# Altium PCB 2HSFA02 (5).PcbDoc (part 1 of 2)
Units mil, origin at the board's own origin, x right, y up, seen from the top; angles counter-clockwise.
Board outline 4391.67 x 3028.12 mil, 2 copper layers (Top Layer, Bottom Layer); 97 components, 133 nets, 219 pads, 38 vias.
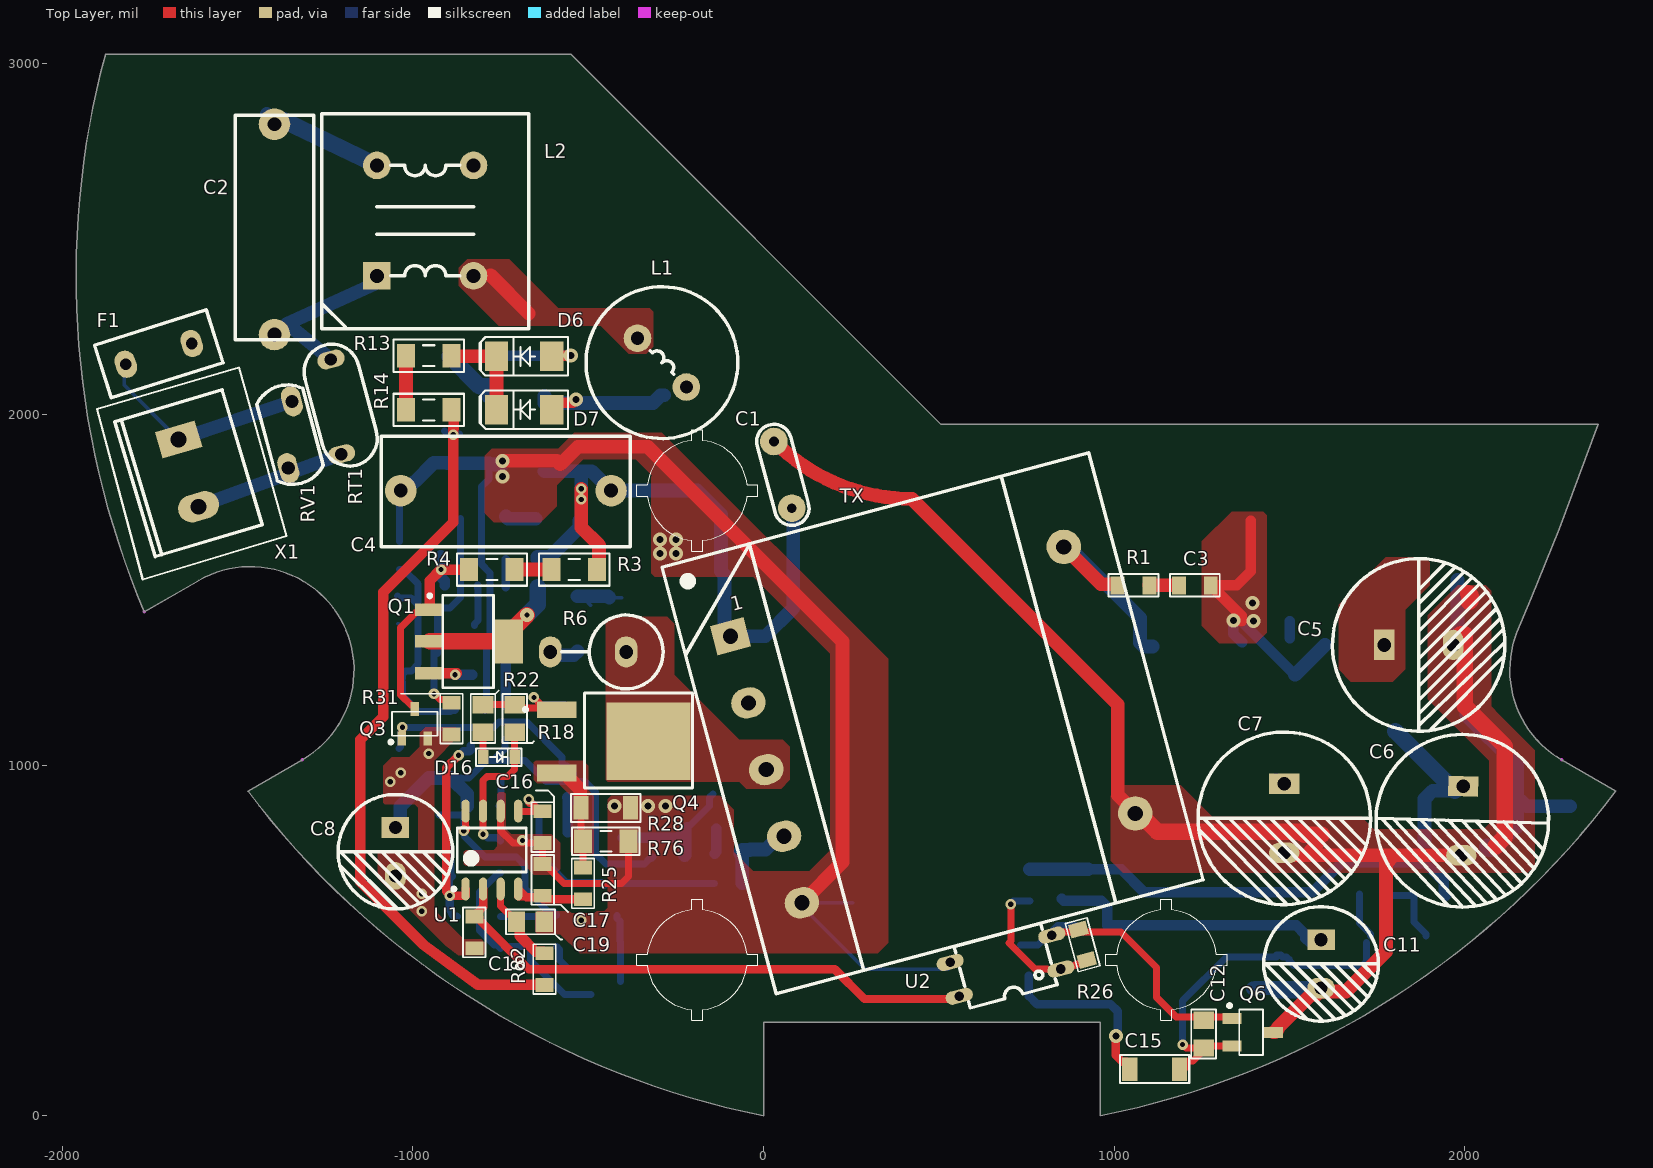
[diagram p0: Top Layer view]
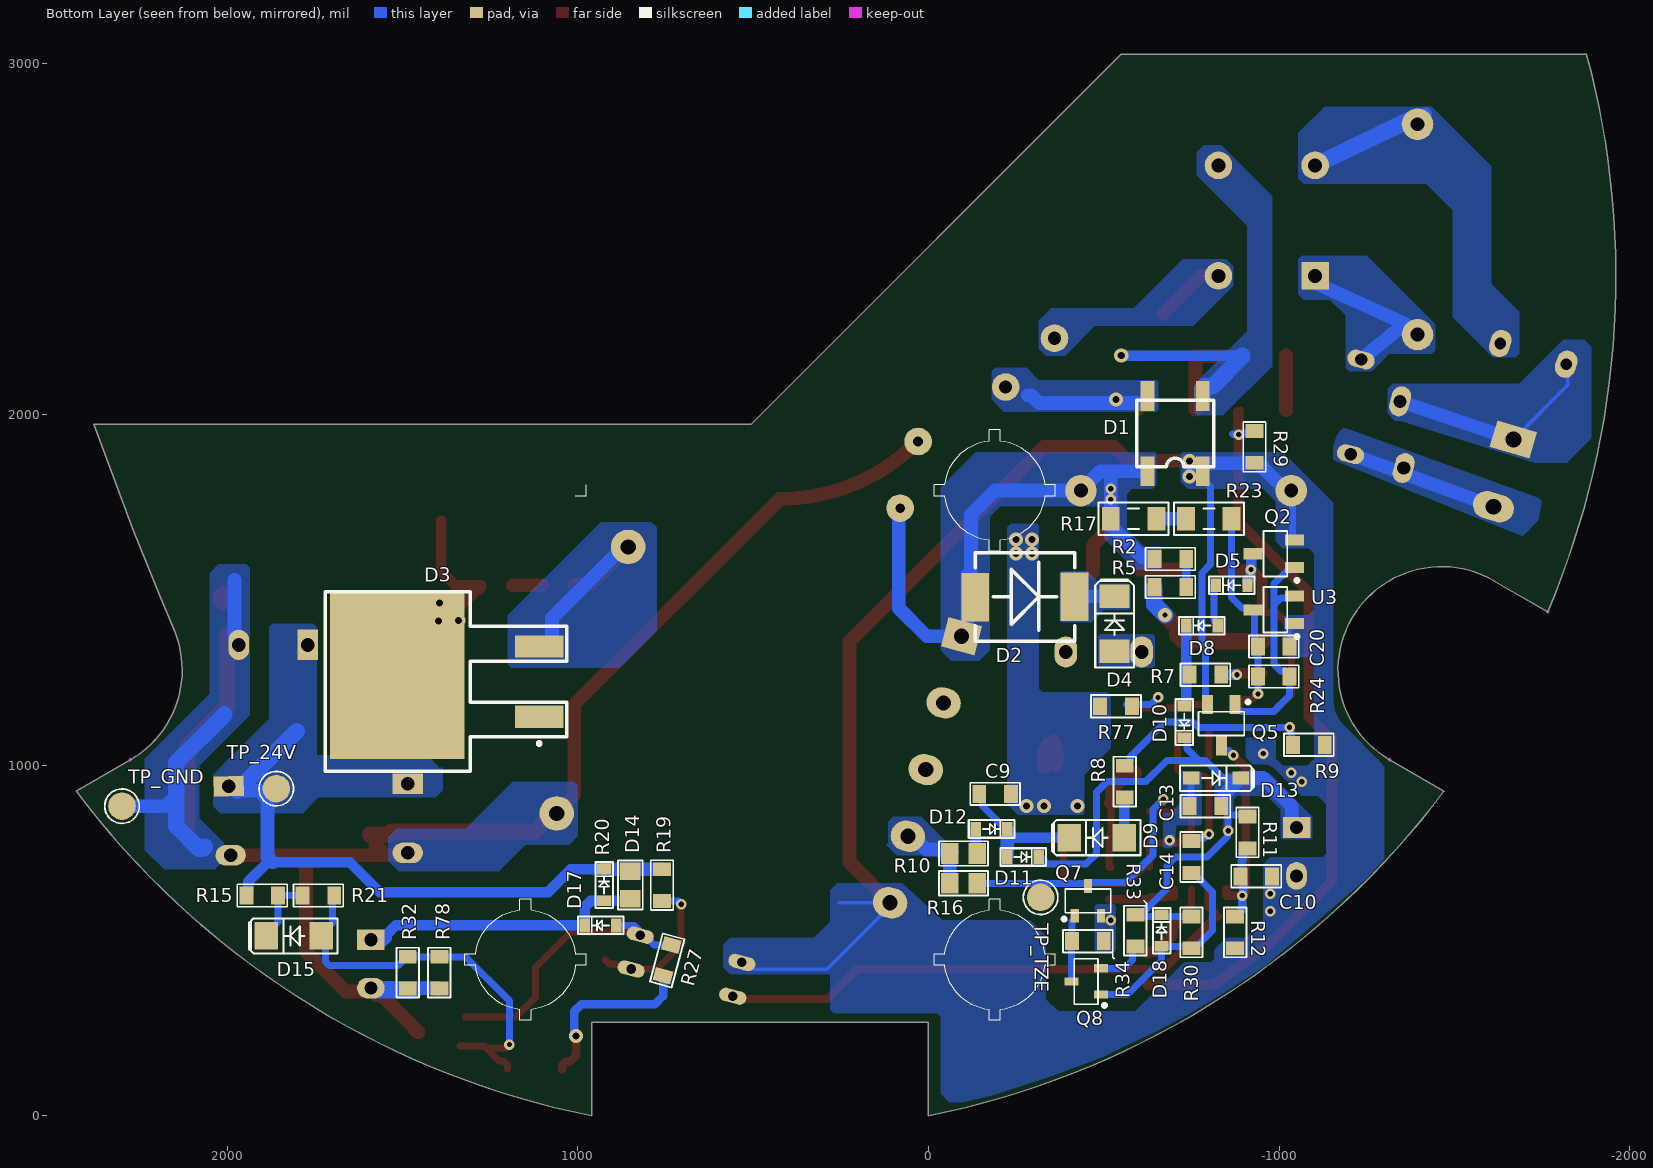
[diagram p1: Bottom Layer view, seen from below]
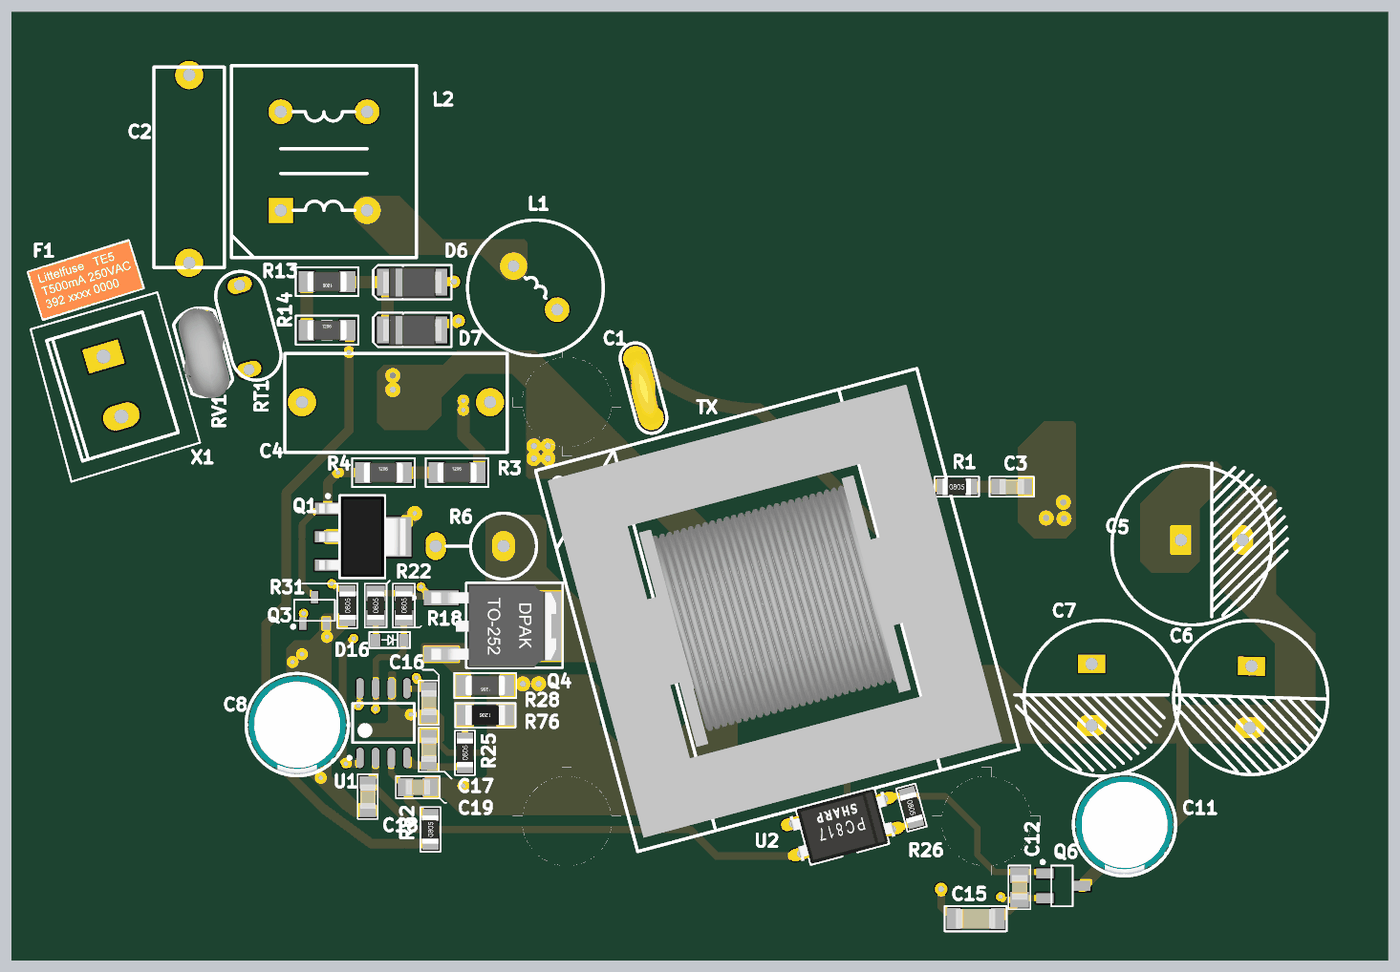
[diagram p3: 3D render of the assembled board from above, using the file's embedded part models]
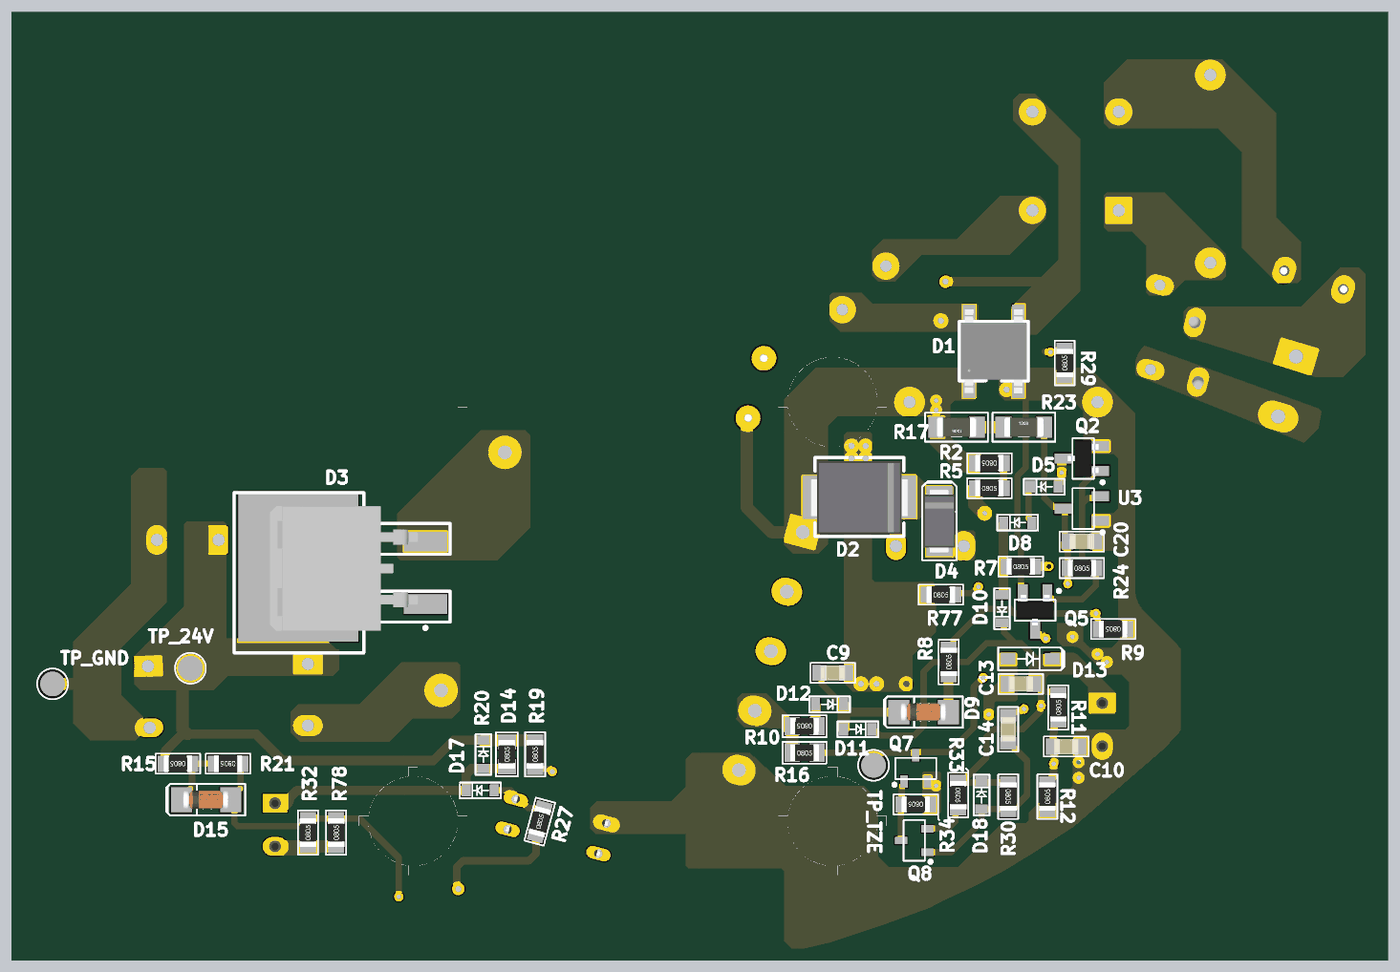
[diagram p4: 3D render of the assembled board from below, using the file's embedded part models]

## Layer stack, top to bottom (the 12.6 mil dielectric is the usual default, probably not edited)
Top Solder: solder mask 0.4, Solder Resist, Dk 3.5
Top Layer: signal copper 1.4
Dielectric 1: dielectric 12.6, FR-4, Dk 4.8
Bottom Layer: signal copper 1.4
Bottom Solder: solder mask 0.4, Solder Resist, Dk 3.5

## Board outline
-1876.79,3028 -550,3028 505,1973 2380,1973 cw(c-7398.82,5437.72) 2148.45,1378.27 ccw(c2423.58,1271.05) 2275.94,1015.34 2430.89,925.87 cw(c480.14,2393.09) 960.45,-0.12 960.45,267.12 -0.18,267.12 -0.18,-0.12 cw(c480.14,2393.1) -1470.62,925.87 -1315.67,1015.34 ccw(c-1463.31,1271.05) -1610.94,1526.77 -1765.9,1437.31 cw(c480.14,2393.1)

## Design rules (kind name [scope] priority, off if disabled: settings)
Clearance [All] p1: gap=8 ignorepadtopadclearanceinfootprint=TRUE except(20: Arc-Fill Arc-Poly Arc-Region Track-Fill Track-Poly Track-Region SMDPad-Fill SMDPad-Poly SMDPad-Region THPad-Fill THPad-Poly THPad-Region Via-Fill Via-Poly Via-Region Fill-Fill Fill-Poly Fill-Region Poly-Poly Poly-Region Region-Region)
PlaneConnect [All] p1: planeconnectstyle=Direct reliefexpansion=20 reliefentries=4 reliefconductorwidth=10 reliefairgap=10
PolygonConnect [All] p1: connectstyle=Direct reliefconductorwidth=10 reliefentries=4 polygonreliefangle="90 Angle" airgapwidth=10
RoutingVias [All] p1: holewidth=20 width=40 viastyle="Through Hole" minholewidth=12 minwidth=24 maxholewidth=28 maxwidth=50
SolderMaskExpansion [All] p1: expansion=4
Width [All] p1: maxlimit=47.24 minlimit=10 preferedwidth=30 minimp=50.000000 maximp=50.000000 favimp=50.000000
29 further rules are at their usual default settings.

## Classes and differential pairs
component class 2HSFA02_Driver: U4

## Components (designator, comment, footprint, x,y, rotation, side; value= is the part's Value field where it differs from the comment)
C1 "Capacitor" "2.2nF, 5mm Pitch" 55,1828 r105 top value=2.2nF/2KV
C2 "Polyester Film Capacitor" "0.47uF 400V,15.24MM" -1395,2828 r270 top value="0.47uF 400V,15.24MM"
C3 "Capacitor" "DNP Cap, 0805-W" 1230.28,1513 r0 top value=DNP
C4 "cap" "0.33uF 520V, 15.24mm" -1035,1783 r0 top
C5 "Cap" "1000uF 35V, D12.5mmxL20mm" 1868.43,1342.91 r0 top
C6 "Cap" "1000uF 35V, D12.5mmxL20mm" 1992.67,841.39 r268.39 top
C7 "Cap" "1000uF 35V, D12.5mmxL20mm" 1485,848.34 r270 top
C8 "8x12.5mm" "47uf 35V, 8x12.5mm"#1 -1050,753 r270 top
C9 "Capacitor" "1uF 50V, 0805-W" -190,918 r0 bottom value="1uF 50V"
C10 "Capacitor" "10nF 50V, 0805-W" -935,683 r0 bottom value="10nF 50V"
C11 "8x12.5mm" "47uf 35V, 8x12.5mm"#2 1590,433 r270 top
C12 "Capacitor" "2.2uF 50V, 0805" 1255,233 r270 top value="2.2uF 50V"
C13 "Capacitor" "100nF 50V, 0805-W" -790,883 r180 bottom value="100nF 50V"
C14 "Capacitor" "33pF 50V, 0805-W" -750,738 r90 bottom value="33pF 50V"
C15 "Capacitor" "10uF 35V, 1206-W" 1115,133 r0 top value="10uF 35V"
C16 "Capacitor" "33pF 50V, 0805-W" -630,823 r90 top value="33pF 50V"
C17 "Capacitor" "100pF 50V, 0805-W" -630,673 r90 top value="100pF 50V"
C18 "Capacitor" "100nF 25V, 0805-W" -825,523 r90 top value="100nF 25V"
C19 "Capacitor" "1nF 50V, 0805" -665,553 r180 top value="1nF 50V"
C20 "Capacitor" "100pF 50V, 0805-W" -985,1338 r0 bottom value="100pF 50V"
D1 "Diode" "ABS210, SOPA-4" -703.74,1945.72 r180 bottom value=ABS210
D2 "TVS 200V" "SMCJ200V, TVS" -275,1478 r0 bottom
D3 "Diode" "STTH803  Diode, D2PAK" 1110,1238 r90 bottom
D4 "Diode" "MURA160T3G, DIODE" -530,1403 r270 bottom
D5 "SOD-323" "BAS20HT1G Diode, SOD-323" -865,1513 r180 bottom
D6 "Diode" "1N4007, SMAF" -683,2166 r0 top value=1N4007
D7 "Diode" "1N4007, SMAF" -683,2014 r0 top value=1N4007
D8 "SOD-323" "BAS20HT1G Diode, SOD-323" -780,1398 r180 bottom
D9 "Diode" "Zener, SOD-80C" -480,793 r180 bottom value=13V
D10 "SOD-323" "BAS20HT1G Diode, SOD-323" -730,1123 r90 bottom
D11 "SOD-323" "BAS20HT1G Diode, SOD-323" -270,738 r0 bottom
D12 "SOD-323" "BAS20HT1G Diode, SOD-323" -180,818 r0 bottom
D13 "Diode" "Zener 18V , SOD-123-W" -820,963 r0 bottom value="Zener 18V"
D14 "SOD-323" "BAS20HT1G Diode, SOD-323" 925,658 r270 bottom
D15 "Diode" "Zener, SOD-80C" 1810,513 r180 bottom value=Zener
D16 "SOD-323" "BAS20HT1G Diode, SOD-323" -755,1023 r180 top
D17 "SOD-323" "BAS20HT1G Diode, SOD-323" 935,543 r180 bottom
D18 "SOD-323" "BAS20HT1G Diode, SOD-323" -665,528 r270 bottom
F1 "Fuse" "Fuse, 4A" -1725,2173 r17.49 top value="4A, 250VAC"
L1 "Inductor" "1mH, 11x16mm" -290,2148 r315 top
L2 "TH" "1.8mH Line Filter, 17x12.3x15.3" -965,2553 r90 top
Q1 "NPN HV transistor" "PBHV2160Z NPN transistor" -840,1353 r0 top
Q2 "Mosfet" "BSS138, SOT-23_W" -985,1603 r90 bottom value=BSS138
Q3 "NPN Transistor" "MMBT3904-7-F, NPN Transistor" -995,1118 r90 top
Q4 "D2PAK" "IPD70R360P7S NMOS DPAK" -427.01,1067.84 r270 top
Q5 "Mosfet" "BSS138, SOT-23_W" -835.63,1113.95 r0 bottom value=BSS138
Q6 "Transistor" "TL431, SOT-23_W" 1395,238 r270 top value=TL431
Q7 "NPN Transistor" "MMBT3904-7-F, NPN Transistor" -455,613 r90 bottom
Q8 "SOT-23" "MMBT3906-7-F PNP, SOT-23" -450,383 r0 bottom
R1 "Resistor" "DNP, 0805-W" 1055,1513 r0 top value=DNP
R2 "Resistor" "10K ±5%, 0805-W" -690,1588 r0 bottom value="10K ±5%"
R3 "Resistor" "1M ±1%, 1206" -540,1558 r0 top value="1M ±1%"
R4 "Resistor" "1M ±1%, 1206" -775,1558 r0 top value="1M ±1%"
R5 "Resistor" "10K ±5%, 0805-W" -690,1508 r180 bottom value="10K ±5%"
R6 "Resistor" "22E, 2W" -500,1323 r180 top value=22E
R7 "Resistor" "220E ±5%, 0805-W" -790,1258 r180 bottom value="220E ±5%"
R8 "Resistor" "10K ±5%, 0805-W" -560,953 r90 bottom value="10K ±5%"
R9 "Resistor" "47K ±5%, 0805-W" -1085,1058 r0 bottom value="47K ±5%"
R10 "0805" "5.11E ± 1%, 0805" -100,748 r0 bottom
R11 "Resistor" "300k ± 1%, 0805-W" -910,808 r90 bottom value=300k
R12 "Resistor" "30K ±1%, 0805-W" -875,523 r90 bottom value="30K ±1%"
R13 "Resistor" "560K ±1%, 1206" -955,2168 r180 top value="560K ±1%"
R14 "Resistor" "560K ±1%, 1206" -955,2013 r0 top value="560K ±1%"
R15 "Resistor" "1K ±1%, 0805-W" 1900,628 r0 bottom value="1K ±1%"
R16 "Resistor" "100K ±1%, 0805" -100,663 r180 bottom value="100K ±1%"
R17 "Resistor" "1M ±1%, 1206" -585,1703 r0 bottom value="1M ±1%"
R18 "0805" "5.11E ± 1%, 0805" -710,1133 r90 top
R19 "Resistor" "4.7K ±1%, 0805-W" 760,658 r90 bottom value="4.7K ±1%"
R20 "Resistor" "100K ±1%, 0805" 850,658 r90 bottom value="100K ±1%"
R21 "Resistor" "390k ± 1%, 0805-W" 1740,628 r0 bottom
R22 "0805" "2.21E ± 1%, 0805" -800,1133 r90 top
R23 "Resistor" "1M ±1%, 1206" -800,1703 r180 bottom value="1M ±1%"
R24 "Resistor" "270k ± 1%, 0805-W" -985,1253 r180 bottom value="270k ± 1%"
R25 "Resistor" "1K ±1%, 0805-W" -515,663 r90 top value="1K ±1%"
R26 "Resistor" "510E ± 5%, 0805-W" 910,488 r285 top value="510E ± 5%"
R27 "Resistor" "4.7K ±1%, 0805-W" 745,443 r105 bottom value="4.7K ±1%"
R28 "1206-W" "0.22E ± 1%, 1206-W" -450,878 r180 top
R29 "Resistor" "7.5K ±5%, 0805-W" -930,1908 r90 bottom value="7.5K ±5%"
R30 "Resistor" "10K ±1%, 0805-W" -750,523 r270 bottom value="10K ±1%"
R31 "Resistor" "13k ± 1%, 0805-W" -890,1132.73 r90 top value="13k ± 1%"
R32 "Resistor" "47K ±5%, 0805-W" 1485,408 r90 bottom value="47K ±5%"
R33 "Resistor" "20K ±5%, 0805-W" -590,528 r270 bottom value="20K ±5%"
R34 "Resistor" "5.1K ±1%, 0805-W" -455,498 r0 bottom value="5.1K ±1%"
R76 "Resistor" "NC, 1206" -450,783 r180 top value=NC
R77 "Resistor" "10K ±5%, 0805-W" -535,1168 r180 bottom value="10K ±5%"
R78 "Resistor" "NC, 0805-W" 1395,408 r90 bottom value=NC
R82 "Resistor" "0E ±5%, 0805-W" -625,418.28 r90 top value="0E ±5%"
RT1 "NTC" "NTC 10E, 7.5/10mm Pitch" -1184,1982 r105 top value="NTC 10E"
RV1 "MOV" "07k385 MOV, 5mm" -1360,1940 r285 top
TP_24V "Test Point" "Test Point 2mm" 1860,933 r270 bottom
TP_GND "Test Point" "Test Point 2mm" 2300,883 r270 bottom
TP_TZE "Test Point" "Test Point 2mm" -320,623 r270 bottom
TX "EE-30 horizontal" "EE-30-H , Transformer" 7.56,987.49 r15 top
U1 "SMD" "UCC28810DR, SOIC8" -775,758 r90 top value=UCC28810
U2 "Optocoupler" "EL817(C)-F, DIP-4" 690,428 r195 top value=EL817
U3 "SMD" TLV803EA26DBZR -985,1443 r90 bottom value=TLV803EA26DBZR
X1 "Connector" "Terminal Block - 2Pin, 5.08mm Pitch" -1640,1833 r286.6 top value="Terminal Block - 2Pin"

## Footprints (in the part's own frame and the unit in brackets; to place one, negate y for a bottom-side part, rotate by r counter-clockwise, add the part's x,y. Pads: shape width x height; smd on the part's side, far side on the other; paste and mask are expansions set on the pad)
"0.22E ± 1%, 1206-W" [mm] "0.25W SMD"
  rect 1.1x1.7 smd: 1(-1.8,0) 2(1.8,0)
  silkscreen extent -2.51,-1.02 2.51,1.02, body extent -1.6,-0.8 1.6,0.8, height 1
"0.33uF 520V, 15.24mm" [mil] "TH"
  round 90 hole 39.37: 1(0,0) 2(600,0)
  silkscreen extent -55,-160 655,155
"0.47uF 400V,15.24MM" [mil]
  round 90 hole 39.37: 1(0,0) 2(600,0)
  silkscreen extent -25,-113 615,113
"0E ±5%, 0805-W" [mm] "Chip Resistor, Body 2.0x1.2mm, IPC Low Density"
  rect 1x1.3 smd mask+0.15: 1(-1.15,0) 2(1.15,0)
  silkscreen extent -1.8,-0.81 1.8,0.81, body extent -1.15,-0.67 1.15,0.68, height 0.76
"1.8mH Line Filter, 17x12.3x15.3" [mm]
  rect 2x2 hole 1: 1(-4,3.5)
  round 2 hole 1: 2(4,3.5) 3(4,-3.5) 4(-4,-3.5)
  silkscreen extent -7.83,-7.5 7.74,7.5
"1K ±1%, 0805-W" [mm] "Chip Resistor, Body 2.0x1.2mm, IPC Low Density"
  rect 1x1.3 smd: 1(-1.15,0) 2(1.15,0)
  silkscreen extent -1.8,-0.81 1.8,0.81, body extent -1.15,-0.67 1.15,0.68, height 0.76
"1M ±1%, 1206" [mm]
  rect 1.3x1.7 smd: 1(-1.65,0) 2(1.65,0)
  silkscreen extent -2.54,-1.17 2.54,1.18, body extent -1.6,-0.8 1.6,0.8, height 1
"1mH, 11x16mm" [mm] "11x16mm"
  round 2 hole 0.95: 1(-2.5,0) 2(2.5,0)
  silkscreen extent -5.5,-5.5 5.5,5.5, body extent -5.5,-5.5 5.5,5.5, height 19
"1N4007, SMAF" [mm] "SMA Diode"
  rect 1.7x2.15 smd mask+0.15: A(2,0) K(-2,0)
  silkscreen extent -3.23,-1.4 3.17,1.4, body extent -2.35,-1.27 2.35,1.23, height 1.03
"1nF 50V, 0805" [mm] "0805"
  rect 1.25x1.5 smd: 1(-1,0) 2(1,0)
  silkscreen extent -1.78,-0.89 1.78,0.89, body extent -1,-0.62 1,0.63, height 0.6
"1uF 50V, 0805-W" [mm]
  rect 1x1.3 smd mask+0.15: 1(-1.15,0) 2(1.15,0)
  silkscreen extent -1.8,-0.81 1.8,0.81, body extent -1,-0.63 1,0.63, height 0.6
"2.2nF, 5mm Pitch" [mm]
  round 2 hole 0.7 mask+0.15: 1(-2.5,0) 2(2.5,0)
  silkscreen extent -3.75,-1.25 3.75,1.25, body extent -3,-1.05 3,1.05, height 8.1
"2.2uF 50V, 0805" [mm] "0805"
  rect 1.25x1.5 smd: 1(-1,0) 2(1,0)
  silkscreen extent -1.78,-0.89 1.78,0.89, body extent -1,-0.62 1,0.63, height 0.6
"2.21E ± 1%, 0805" [mm] "0.125W SMD"
  rect 1.25x1.5 smd: 1(-1,0) 2(1,0)
  silkscreen extent -1.78,-0.89 1.78,0.89, body extent -1.15,-0.67 1.15,0.68, height 0.76
"4.7K ±1%, 0805-W" [mm] "Chip Resistor, Body 2.0x1.2mm, IPC Low Density"
  rect 1x1.3 smd mask+0.15: 1(-1.15,0) 2(1.15,0)
  silkscreen extent -1.8,-0.81 1.8,0.81, body extent -1.15,-0.67 1.15,0.68, height 0.76
"5.1K ±1%, 0805-W" [mm] "Chip Resistor, Body 2.0x1.2mm, IPC Low Density"
  rect 1x1.3 smd mask+0.15: 1(-1.15,0) 2(1.15,0)
  silkscreen extent -1.8,-0.81 1.8,0.81, body extent -1.15,-0.67 1.15,0.68, height 0.76
"5.11E ± 1%, 0805" [mm] "0.125W SMD"
  rect 1.25x1.5 smd: 1(-1,0) 2(1,0)
  silkscreen extent -1.78,-0.89 1.78,0.89, body extent -1.15,-0.67 1.15,0.68, height 0.76
"7.5K ±5%, 0805-W" [mm] "Chip Resistor, Body 2.0x1.2mm, IPC Low Density"
  rect 1x1.3 smd: 1(-1.15,0) 2(1.15,0)
  silkscreen extent -1.8,-0.81 1.8,0.81, body extent -1.15,-0.67 1.15,0.68, height 0.76
"07k385 MOV, 5mm" [mm] "TH"
  oval 2.2x1.4 hole 0.95: 1(-2.3,1) 2(2.3,-0.5)
  silkscreen extent -3.61,-1.5 3.61,2, body extent -3.65,-1.62 3.85,2.22, height 11.25
"10K ±1%, 0805-W" [mm] "Chip Resistor, Body 2.0x1.2mm, IPC Low Density"
  rect 1x1.3 smd mask+0.15: 1(-1.15,0) 2(1.15,0)
  silkscreen extent -1.8,-0.81 1.8,0.81, body extent -1.15,-0.67 1.15,0.68, height 0.76
"10K ±5%, 0805-W" [mm] "Chip Resistor, Body 2.0x1.2mm, IPC Low Density"
  rect 1x1.3 smd mask+0.15: 1(-1.15,0) 2(1.15,0)
  silkscreen extent -1.8,-0.81 1.8,0.81, body extent -1.15,-0.67 1.15,0.68, height 0.76
"10nF 50V, 0805-W" [mm]
  rect 1x1.3 smd: 1(-1.15,0) 2(1.15,0)
  silkscreen extent -1.8,-0.81 1.8,0.81, body extent -1,-0.62 1,0.63, height 0.6
"10uF 35V, 1206-W" [mm]
  rect 1.1x1.7 smd mask+0.15: 1(-1.8,0) 2(1.8,0)
  silkscreen extent -2.51,-1.02 2.51,1.02, body extent -1.6,-0.8 1.6,0.8, height 0.79
"13k ± 1%, 0805-W" [mm] "SMD"
  rect 1x1.3 smd: 1(-1.15,0) 2(1.15,0)
  silkscreen extent -1.8,-0.81 1.8,0.81, body extent -1.15,-0.67 1.15,0.68, height 0.76
"20K ±5%, 0805-W" [mm] "Chip Resistor, Body 2.0x1.2mm, IPC Low Density"
  rect 1x1.3 smd: 1(-1.15,0) 2(1.15,0)
  silkscreen extent -1.8,-0.81 1.8,0.81, body extent -1.15,-0.67 1.15,0.68, height 0.76
"22E, 2W" [mm] "2 Leads, vertical"
  oval 1.65x2.25 hole 1: 1(-2.75,0) 2(2.75,0)
  silkscreen extent -5.42,-2.67 1.91,2.67
"30K ±1%, 0805-W" [mm] "Chip Resistor, Body 2.0x1.2mm, IPC Low Density"
  rect 1x1.3 smd mask+0.15: 1(-1.15,0) 2(1.15,0)
  silkscreen extent -1.8,-0.81 1.8,0.81, body extent -1.15,-0.67 1.15,0.68, height 0.76
"33pF 50V, 0805-W" [mm] "Chip Resistor, Body 2.0x1.2mm, IPC Low Density"
  rect 1x1.3 smd: 1(-1.15,0) 2(1.15,0)
  silkscreen extent -1.8,-0.81 1.8,0.81, body extent -1,-0.62 1,0.63, height 0.6
"47K ±5%, 0805-W" [mm] "Chip Resistor, Body 2.0x1.2mm, IPC Low Density"
  rect 1x1.3 smd: 1(-1.15,0) 2(1.15,0)
  silkscreen extent -1.8,-0.81 1.8,0.81, body extent -1.15,-0.67 1.15,0.68, height 0.76
"47uf 35V, 8x12.5mm"#1 [mm] "8x12.5mm"
  rect 1.5x2 hole 0.95: 1(-1.75,0)
  oval 2x1.5 hole 0.95: 2(1.75,0)
  silkscreen extent -4.15,-4.15 4.15,4.15, body extent -3.99,-4 4.02,4, height 12.51
"47uf 35V, 8x12.5mm"#2 [mm] "8x12.5mm"
  rect 1.5x2 hole 0.95: 1(-1.75,0)
  oval 1.5x2 hole 0.95: 2(1.75,0)
  silkscreen extent -4.15,-4.15 4.15,4.15, body extent -3.99,-4 4.02,4, height 12.51
"100K ±1%, 0805" [mm]
  rect 1.25x1.5 smd: 1(-1,0) 2(1,0)
  silkscreen extent -1.78,-0.89 1.78,0.89, body extent -1.15,-0.67 1.15,0.68, height 0.76
"100nF 25V, 0805-W" [mm]
  rect 1x1.3 smd mask+0.15: 1(-1.15,0) 2(1.15,0)
  silkscreen extent -1.8,-0.81 1.8,0.81, body extent -1,-0.62 1,0.63, height 0.6
"100nF 50V, 0805-W" [mm]
  rect 1x1.3 smd mask+0.15: 1(-1.15,0) 2(1.15,0)
  silkscreen extent -1.8,-0.81 1.8,0.81, body extent -1,-0.62 1,0.63, height 0.6
"100pF 50V, 0805-W" [mm] "Chip Resistor, Body 2.0x1.2mm, IPC Low Density"
  rect 1x1.3 smd: 1(-1.15,0) 2(1.15,0)
  silkscreen extent -1.8,-0.81 1.8,0.81, body extent -1,-0.62 1,0.63, height 0.6
"220E ±5%, 0805-W" [mm] "Chip Resistor, Body 2.0x1.2mm, IPC Low Density"
  rect 1x1.3 smd: 1(-1.15,0) 2(1.15,0)
  silkscreen extent -1.8,-0.81 1.8,0.81, body extent -1.15,-0.67 1.15,0.68, height 0.76
"270k ± 1%, 0805-W" [mm] "SMD"
  rect 1x1.3 smd: 1(-1.15,0) 2(1.15,0)
  silkscreen extent -1.8,-0.81 1.8,0.81, body extent -1.15,-0.67 1.15,0.68, height 0.76
"300k ± 1%, 0805-W" [mm] "0805-W"
  rect 1x1.3 smd: 1(-1.15,0) 2(1.15,0)
  silkscreen extent -1.8,-0.81 1.8,0.81, body extent -1.15,-0.67 1.15,0.68, height 0.76
"390k ± 1%, 0805-W" [mm] "0805-W"
  rect 1x1.3 smd: 1(-1.15,0) 2(1.15,0)
  silkscreen extent -1.8,-0.81 1.8,0.81, body extent -1.15,-0.67 1.15,0.68, height 0.76
"510E ± 5%, 0805-W" [mm] "SMD"
  rect 1x1.3 smd mask+0.15: 1(-1.15,0) 2(1.15,0)
  silkscreen extent -1.8,-0.81 1.8,0.81, body extent -1.15,-0.67 1.15,0.68, height 0.76
"560K ±1%, 1206" [mm]
  rect 1.3x1.7 smd: 1(-1.65,0) 2(1.65,0)
  silkscreen extent -2.54,-1.17 2.54,1.17, body extent -1.6,-0.8 1.6,0.8, height 1
"1000uF 35V, D12.5mmxL20mm" [mm] "TH"
  rect 1.5x2.2 hole 1: 1(-2.5,0.002)
  oval 1.5x2.2 hole 1: 2(2.5,0.002)
  silkscreen extent -6.25,-6.25 6.25,6.25, body extent -6.25,-6.24 6.25,6.25, height 20
"ABS210, SOPA-4" [mm]
  rect 1x2.15 smd: 1(-2,-2.725) 2(-2,2.725) 3(2,-2.725) 4(2,2.725)
  silkscreen extent -2.79,-2.41 2.79,2.41, body extent -2.66,-3.41 2.66,3.41, height 1.5
"BAS20HT1G Diode, SOD-323" [mm] "Switching Diode"
  rect 0.75x1 smd: A(1.143,0) K(-1.143,0)
  silkscreen extent -1.65,-0.64 1.65,0.64
"BSS138, SOT-23_W" [mm] "SOT23, 3-Leads, Body 2.9x1.3mm, Pitch 0.95mm, Lead Span 2.5mm, IPC High Density"
  rect 0.8x1.4 smd mask+0.15: 1(-1,-1.5) 2(1,-1.5) 3(0,1.5)
  silkscreen extent -2.06,-1.8 1.65,0.75, body extent -1.5,-1.36 1.5,1.14, height 1.1
"DNP Cap, 0805-W" [mm]
  rect 1x1.3 smd mask+0.15: 1(-1.15,0) 2(1.15,0)
  silkscreen extent -1.8,-0.81 1.8,0.81, body extent -1,-0.62 1,0.63, height 0.6
"DNP, 0805-W" [mm] "Chip Resistor, Body 2.0x1.2mm, IPC Low Density"
  rect 1x1.3 smd mask+0.15: 1(-1.15,0) 2(1.15,0)
  silkscreen extent -1.8,-0.81 1.8,0.81, body extent -1.15,-0.67 1.15,0.68, height 0.76
"EE-30-H , Transformer" [mm] "TH"
  rect 2.5x2.2 hole 1.1: 1(0,10)
  oval 2.5x2.2 hole 1.1: 2(0,5) 3(0,0) 4(0,-5) 5(0,-9.99)
  round 2.5 hole 1.1: 6(25,-9.99) 10(25,10)
  silkscreen extent -3.5,-15.89 28.5,16.12, body extent -2.75,-14.93 27.35,15.07, height 19
"EL817(C)-F, DIP-4" [mm] "Optocoupler"
  oval 2x1 hole 0.7: 1(-3.81,1.27) 2(-3.81,-1.27) 3(3.81,-1.27) 4(3.81,1.27)
  silkscreen extent -3.25,-2.3 3.25,2.3, body extent -3.94,-2.3 3.94,2.3, height 4.3
"Fuse, 4A" [mm] "Box Type"
  oval 1.5x2 hole 0.85 mask+0.15: 1(-2.5,0) 2(2.5,0)
  silkscreen extent -4.25,-2 4.25,2, body extent -4.25,-2 4.25,2, height 8
"IPD70R360P7S NMOS DPAK" [mm] "SMD"
  rect 1.2x2.83 smd: 1(-2.29,-4.14) 3(2.29,-4.14)
  rect 5.63x6.09 smd: 2(0,2.51)
  silkscreen extent -3.51,-6.5 3.38,5.69, body extent -3.37,-4.96 3.37,5.15, height 2.37
"MMBT3904-7-F, NPN Transistor" [mm] "SOT-23"
  rect 1x0.6 smd: 1(-1.075,0.95) 2(-1.075,-0.95) 3(1.075,0)
  silkscreen extent -1.45,-1.65 0.86,1.85, body extent -1.25,-1.5 1.25,1.5, height 1.1
"MMBT3906-7-F PNP, SOT-23" [mm] "SOT-23 SMD"
  rect 1x0.6 smd: 1(-1.075,0.95) 2(-1.075,-0.95) 3(1.075,0)
  silkscreen extent -1.45,-1.65 0.86,1.85, body extent -1.25,-1.5 1.25,1.5, height 1.1
"MURA160T3G, DIODE" [mm] "SMA"
  rect 1.7x2.15 smd: A(2,0.021) K(-2,0.021)
  silkscreen extent -3.23,-1.38 3.18,1.42, body extent -2.6,-1.3 2.6,1.3, height 2.5
"NC, 0805-W" [mm] "Chip Resistor, Body 2.0x1.2mm, IPC Low Density"
  rect 1x1.3 smd: 1(-1.15,0) 2(1.15,0)
  silkscreen extent -1.8,-0.81 1.8,0.81, body extent -1.15,-0.67 1.15,0.68, height 0.76
"NC, 1206" [mm]
  rect 1.3x1.7 smd: 1(-1.65,0) 2(1.65,0)
  silkscreen extent -2.44,-0.99 2.44,0.99, body extent -1.6,-0.8 1.6,0.8, height 0.6
"NTC 10E, 7.5/10mm Pitch" [mm] "10E"
  oval 1.25x2 hole 0.9 mask+0.15: 1(-2.199,1.115) 2(4.622,0.076)
  silkscreen extent -3.25,-1.75 5.75,2.26
"PBHV2160Z NPN transistor" [mm] "SOT-223"
  rect 2.1x0.9 smd mask+0.15: 1(-2.85,2.3) 2(-2.85,0) 3(-2.85,-2.3)
  rect 2.1x3.2 smd mask+0.15: 4(2.85,0)
  silkscreen extent -2.97,-3.35 1.78,3.42, body extent -3.55,-3.25 3.45,3.25, height 1.68
"SMCJ200V, TVS" [mm] "DO214AB/SMC"
  rect 2x3.5 smd: A(3.604,-0.032) K(-3.6,-0.05)
  silkscreen extent -3.6,-3.25 3.6,3.15, body extent -3.97,-2.95 3.98,2.95, height 2.5
"STTH803  Diode, D2PAK" [mm] "D2PAK"
  rect 1.6x3.5 smd: A(2.54,0) NC(-2.54,0)
  rect 12.2x9.75 smd: K(0.5,10.3)
  silkscreen extent -6.5,-2 6.5,15.5, body extent -4.7,0.6 5.4,12.6, height 5.48
"Terminal Block - 2Pin, 5.08mm Pitch" [mm] "Header; 2 Position, 1729128(Part No)"
  rect 2x3 hole 1.15 mask+0.15: 1(-2.54,0)
  oval 2x3 hole 1.15 mask+0.15: 2(2.54,0)
  silkscreen extent -5.1,-4.05 5.1,4.05
"Test Point 2mm" [mm]
  round 2 smd mask+0.15: TP(0,0)
  silkscreen extent -1.25,-1.25 1.25,1.25
"TL431, SOT-23_W" [mm] "SOT23, 3-Leads, Body 2.9x1.3mm, Pitch 0.95mm, Lead Span 2.5mm, IPC High Density"
  rect 0.8x1.4 smd mask+0.15: A(0,1.5) K(-1,-1.5) REF(1,-1.5)
  silkscreen extent -2.06,-1.8 1.65,0.75, body extent -1.5,-1.36 1.5,1.14, height 1.1
TLV803EA26DBZR [mm] "SMD, SOT-23-3"
  rect 0.8x1.4 smd mask+0.15: 1(-1,-1.5) 2(1,-1.5) 3(0,1.5)
  silkscreen extent -2.06,-1.8 1.65,0.75, body extent -1.5,-1.36 1.5,1.14, height 1.1
"UCC28810DR, SOIC8" [mm] "SMD, SOIC-8"
  oval 1.65x0.6 smd: 1(-2.825,1.905) 2(-2.825,0.635) 3(-2.825,-0.635) 4(-2.825,-1.905) 5(2.825,-1.905) 6(2.825,-0.635) 7(2.825,0.635) 8(2.825,1.905)
  silkscreen extent -2.95,-2.5 1.6,2.88, body extent -3,-2.5 3,2.5, height 1.5
"Zener 18V , SOD-123-W" [mm]
  rect 1.2x0.95 smd mask+0.15: A(1.8,0) K(-1.8,0)
  silkscreen extent -2.77,-0.91 2.59,0.94, body extent -1.93,-0.84 1.93,0.86, height 1.42
"Zener, SOD-80C" [mm] "Zener Diode"
  rect 1.7x2 smd: A(2,0) K(-2,0)
  silkscreen extent -3.23,-1.27 3.18,1.27, body extent -1.88,-0.8 1.82,0.8, height 1.6

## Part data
C1: library part "2.2nF/2KV, 5mm Pitch", "TH", DisplayValue=2.2nF/2KV
C2: library part "0.47uF 400V,15.24MM", "TH", DisplayValue="0.47uF 400V"
C3: library part "DNP Cap, 0805-W", "SMD", DisplayValue=DNP
C4: library part "0.33uF 520V, 15.24mm", "18mm X 14.5 X 8.5mm", DisplayValue="0.33uF 520V"
C5 C6 C7: library part "1000uF 35V, D12.5mmxL20mm", DisplayValue="1000uF 35V"
C8 C11: library part "47uF 35V, 8x11mm", "8mm x 12.5mm", DisplayValue="47uF 35V"
C9: library part "1uF 50V, 0805-W", "SMD", DisplayValue=1uF
C10: library part "10nF 50V, 0805-W", "SMD", DisplayValue=10nF
C12: library part "2.2uF 50V, 0805", "SMD", DisplayValue="2.2uF 50V"
C13: library part "100nF 50V, 0805-W", "SMD", DisplayValue=100nF
C14 C16: library part "33pF 50V, 0805-W", "SMD", DisplayValue=33pF
C15: library part "10uF 35V, 1206-W", "SMD", DisplayValue="10uF 35V"
C17 C20: library part "100pF 50V, 0805-W", "SMD", DisplayValue=100pF
C18: library part "100nF 25V, 0805-W", "SMD", DisplayValue=100nF
C19: library part "1nF 50V, 0805", "SMD", DisplayValue=1nF
D1: library part "ABS210, SOPA-4", "SMD", DisplayValue=ABS210
D2: library part "TVS, SMCJ200A, DO214AB/SMC", "SMD", DisplayValue="200V TVS"
D3: library part "STTH803 Diode, D2PAK", "D2PAK", DisplayValue=STTH803
D4: library part "MURA160T3G, SMA", "SMA", DisplayValue=MURAT160T3G
D5 D8 D10 D11 D12 D14 D17 D18: library part "BAS20HT1G diode, SOD-323", "200V 0.2A Switching Diode SMD SOD-323", DisplayValue=BAS20HT1G
D6 D7: library part "1N4007, SMAF", "SMD", DisplayValue=1N4007
D9: library part "Zener, SOD-80C", "SMD", DisplayValue=Zener
D13: library part "Zener 18V , SOD-123-W", "SMD", DisplayValue="Zener 18V"
D15: library part "Zener, SOD-80C", "SMD", DisplayValue=24V
D16: library part "BAS20HT1G diode, SOD-323", "200V 0.2A Switching Diode SMD SOD-323"
F1: library part "Fuse, 4A", "TH", DisplayValue="4A, 250VAC"
L1: library part "1mH, 11x16mm", "TH", DisplayValue=1mH
L2: library part "1.8mH Line Filter, 17x12.3x15.3", DisplayValue=1.8mH
Q1: library part "PBHV2160Z-NPN Transistor, SOT-223", "600V 0.1A High Voltage NPN Transistor SOT-223", DisplayValue=PBHV2160Z
Q2 Q5: library part "BSS138, SOT-23_W", "SMD", DisplayValue=BSS138
Q3 Q7: library part "MMBT3904-7-F NPN, SOT23", "40V 0.2A NPN Transistor SOT-23", DisplayValue=mmbt3904
Q4: library part "IPD70R360P7S NMOS, D2PAK", "NPN POWER MOSFET 700V", DisplayValue=IPD70R360P7S
Q6: library part "TL431, SOT-23_W", "SMD", DisplayValue=TL431
Q8: library part "MMBT3906-7-F, PNP SOT-23", "40V 0.2A PNP Transistor SOT-23", DisplayValue=MMBT3906
R1: library part "DNP, 0805-W", "SMD", DisplayValue=DNP
R2 R5 R8 R77: library part "10K ±5%, 0805-W", "SMD", DisplayValue=10K
R3 R4 R17 R23: library part "1M ±1%, 1206", "SMD", DisplayValue=1M
R6: library part "22E, 2W", "TH", DisplayValue=22E
R7: library part "220E ±5%, 0805-W", "SMD", DisplayValue=220E
R9 R32: library part "47K ±5%, 0805-W", "SMD", DisplayValue=47K
R10 R18: library part "5.11E ± 1%, 0805", "0.125W SMD", DisplayValue=5.11E
R11: library part "300k  ± 1%, 0805-W", "SMD", DisplayValue=300k
R12: library part "30K ±1%, 0805-W", "SMD", DisplayValue=30K
R13 R14: library part "560K ±1%, 1206", "SMD", DisplayValue=560K
R15 R25: library part "1K ±1%, 0805-W", "SMD", DisplayValue=1K
R16 R20: library part "100K ±1%, 0805", "SMD", DisplayValue=100K
R19 R27: library part "4.7K ±1%, 0805-W", "SMD", DisplayValue=4.7K
R21: library part "390k ± 1%, 0805-W", "SMD", DisplayValue=390k
R22: library part "2.21E ± 1%, 0805", "0.125W SMD", DisplayValue=2.21E
R24: library part "270k ± 1%, 0805-W", "SMD", DisplayValue=270k
R26: library part "510E ± 5%, 0805-W", "SMD", DisplayValue=510E
R28: library part "0.22E ± 1%, 1206-W", "0.25W SMD", DisplayValue=0.22E
R29: library part "7.5K ±5%, 0805-W", "SMD", DisplayValue=7.5K
R30: library part "10K ±1%, 0805-W", "SMD", DisplayValue=10K
R31: library part "13k ± 1%, 0805-W", "SMD", DisplayValue=13k
R33: library part "20K ±5%, 0805-W", "SMD", DisplayValue=20K
R34: library part "5.1K ±1%, 0805-W", "SMD", DisplayValue=5.1K
R76: library part "NC, 1206", "SMD", DisplayValue=NC, Manufacturer=NA
R78: library part "NC, 0805-W", "SMD", DisplayValue=NC, Manufacturer=NA
R82: library part "0E ±5%, 0805-W", "SMD", DisplayValue=0E
RT1: library part "NTC 10E, 7.5/10mm Pitch", "TH", DisplayValue=10E
RV1: library part "07k385 MOV, 5mm", "TH", DisplayValue=07k385
TP_24V TP_GND TP_TZE: "Test Point_2mm", DisplayValue=TP
TX: library part "EE30-H, 470uH transformer", "TH", DisplayValue=EE-30-H
U1: library part UCC28810,SOIC8, "POWER CONTOLLER IC SOIC8"
U2: library part "EL817(C)-F, DIP-4", "TH", DisplayValue=EL817
U3: library part "TLV803EA26DBZR, SOT-23", "UVLO SMD"
X1: library part "Terminal Block - 2Pin, 5.08mm Pitch", "TH", DisplayValue="TB - 2Pin", Manufacturer="Phoenix Contact", Part Number=1729128

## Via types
v1: diameter 30, hole 15, Top Layer to Bottom Layer, 22 vias
v2: diameter 40, hole 20, Top Layer to Bottom Layer, 15 vias
v3: diameter 39.37, hole 15, Top Layer to Bottom Layer, 1 vias

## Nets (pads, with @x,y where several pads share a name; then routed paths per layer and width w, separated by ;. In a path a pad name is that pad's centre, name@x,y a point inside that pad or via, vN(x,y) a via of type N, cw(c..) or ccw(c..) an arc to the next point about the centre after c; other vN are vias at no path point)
+3V3: 
+5V: 
+24V: C3.2 C5.1 C6.1 C7.1 D3.K D14.K R15.2 R19.2 R20.2 TP_24V.TP | length 2779
  Top Layer w30: v2(1340,1413) 1360,1413 1363.09,1409.91 1363.09,1425.46 1286.14,1502.41 1280.24,1502.41 1275.55,1507.1 C3.2@1275.55,1513 1350,1513 1390,1553 1390,1697.13
  Bottom Layer w30: D14.K@924.72,703.28 1019.72,703.28 1085,638 1565,638 1650,723 1870,723 ; D3.K@1365,1349.89 1340,1374.89 v2(1340,1413) 1360.2,1413 1390,1383.2 D3.K@1515.51,1257.68 ; D3.K@1500.51,1362.68 D3.K@1500.51,1410.91 ; 1877.5,730.5 1940.59,667.41 1940.59,632.69 R15.2@1945.28,628
  Bottom Layer w39.37: R19.2@760,703.28 924.72,703.28 D14.K@925,703 ; C7.1@1461.47,956.61 1471.31,946.77 C7.1@1485.09,946.77 ; D3.K@1515.51,1257.68 D3.K@1600.83,1343 ; 1870,723 1877.5,730.5 1885.28,738.28 1885.28,903.99 1908.34,927.05 C6.1@1971.68,927.05
  Bottom Layer w47.24: 1801.74,1096.99 C6.1@1971.68,927.05
  other v2: 1396.91,1411.09 1395,1463
AGND: 
AVDD: 
B_LED: 
BUZZER: 
DVDD: 
EAOUT: C18.2 U1.2 U2.4 | length 1557.3
  Top Layer w24: C18.2@-825,568.28 C18.2@-819.09,568.28 ; C18.2@-816.41,578.62 -800,595.03 U1.2@-800,646.78 ; C18.2@-814.09,568.28 -811.41,565.59 -811.41,559.41 -670,418 202.88,418 287.88,333 550.17,333 U2.4@558.05,340.88
ESP_BLUE: 
esp_en: 
ESP_GREEN: 
ESP_RED: 
esp_rst: 
ESP_RX: 
ESP_TX: 
FB_BK: 
G_LED: 
HVGND: C4.1 C8.2 C9.1 C10.1 C13.1 C16.1 C17.2 C18.1 C19.1 C20.1 D1.3 D13.A Q2.2 Q3.2 Q5.2 Q7.2 R9.1 R12.1 R28.1 R29.1 R31.1 R34.1 R76.1 R77.1 TX.5 U1.6 U2.3 U3.1 | length 4638.4
  Top Layer w20: U1.6@-750,869.22 -750,813 -714.72,777.72 C16.1@-630,777.72 C17.2@-630,718.28 ; C17.2@-630,708.28 C17.2@-630,718.28 ; R76.1@-385.04,783 -385.04,682.96 -405,663 -568.82,663 -624.09,718.28 C17.2@-630,718.28
  Top Layer w39.37: v2(-745,1868) -590,1868 -580,1858 -530,1908 -330,1908 225,1353 225,723.23 TX.5@109.35,607.58
  Bottom Layer w10: U3.1@-1044.06,1403.63 -1041.02,1403.63 -1030.28,1392.88 C20.1@-1030.28,1338 ; 254.58,607.58 TX.5@109.35,607.58 109.35,598.29 289.42,418.22 U2.3@512.92,418.22 ; U2.3@527.08,418.22 U2.3@512.92,418.22 ; U2.3@532.17,437.47 U2.3@512.92,418.22
  Bottom Layer w20: Q2.2@-1039.06,1637.37 C4.1@-1039.06,1763.32 ; Q5.2@-800.63,1162.06 Q5.2@-794.88,1156.31 ; Q5.2@-796.26,1173 -790.51,1178.75 -790.51,1342.49 -780,1353 -780,1548 -805,1573 -805,1794.4 -793.28,1806.11 -792.17,1806.11 -782.48,1815.8 D1.3@-782.48,1838.43 ; C13.1@-754.72,883 -749.13,888.59 D13.A@-749.13,963
  Bottom Layer w39.37: C4.1@-1035,1783 -1021.3,1783 -995.98,1808.31 -994.69,1808.31 -940.28,1862.72 R29.1@-930,1862.72 R29.1@-910,1862.72 ; -904.09,1862.72 -902.44,1861.07 D1.3@-782.48,1861.07 ; D1.3@-782.48,1857.88 -745.12,1857.88 -745,1858 v2(-745,1868)
  other v1: -520,558 -975,583 -975,633 -687.66,785.35 -1065,953 -1035,978 -955,1033
  other v2: -425,883 -330,883 -280,883 -295,1603 -250,1603 -295,1643 -250,1643 -745,1823
ICPCLK: 
ICPDA: 
IO0: 
NetBLDC1_1: 
NetBLDC1_2: 
NetBLDC1_3: 
NetBZ1_1: 
NetC1_1: C1.1 C4.2 D1.1 D2.A R2.2 R3.2 R17.2 TX.1 | length 2010.4
  Top Layer w39.37: v1(-520,1788) -520,1678 -469.43,1627.43 -469.43,1551.09 R3.2@-469.13,1550.79
  Bottom Layer w10: C1.1@80.47,1732.93 84.37,1729.03 C1.1@88.27,1725.14
  Bottom Layer w39.37: R2.2@-644.72,1588 -644.72,1593.91 -609.09,1593.91 -525.94,1677.06 -525.94,1697.09 R17.2@-520.04,1703 ; D1.1@-625,1838.43 -530,1838.43 ; R17.2@-520.04,1695.13 v1(-520,1758) v1(-520,1788) -520.04,1828.47 -530,1838.43 ; C1.1@84.37,1729.03 84.37,1447.37 4.77,1367.77 TX.1@-94.34,1367.77 -111.37,1384.8 -111.37,1479.26 -111.37,1542.3 -121.85,1552.78 -121.85,1714.85 -190,1783 C4.2@-435,1783 -490.43,1838.43 -530,1838.43
NetC2_1: C2.1 F1.2 L2.2 | length 643.2
  Bottom Layer w39.37: C2.1@-1417,2857 -1371.82,2835.24 L2.2@-1112.8,2710.48 ; C2.1@-1368.05,2843.06 -1109.03,2718.3 L2.2@-1092.8,2710.48
NetC2_2: C2.2 L2.1 RT1.2 | length 453.8
  Bottom Layer w39.37: RT1.2@-1234,2157 -1359,2259 L2.1@-1092.8,2380.22
NetC3_1: C3.1 R1.2 | length 84.7
  Top Layer w39.37: R1.2@1100.28,1513 C3.1@1185,1513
